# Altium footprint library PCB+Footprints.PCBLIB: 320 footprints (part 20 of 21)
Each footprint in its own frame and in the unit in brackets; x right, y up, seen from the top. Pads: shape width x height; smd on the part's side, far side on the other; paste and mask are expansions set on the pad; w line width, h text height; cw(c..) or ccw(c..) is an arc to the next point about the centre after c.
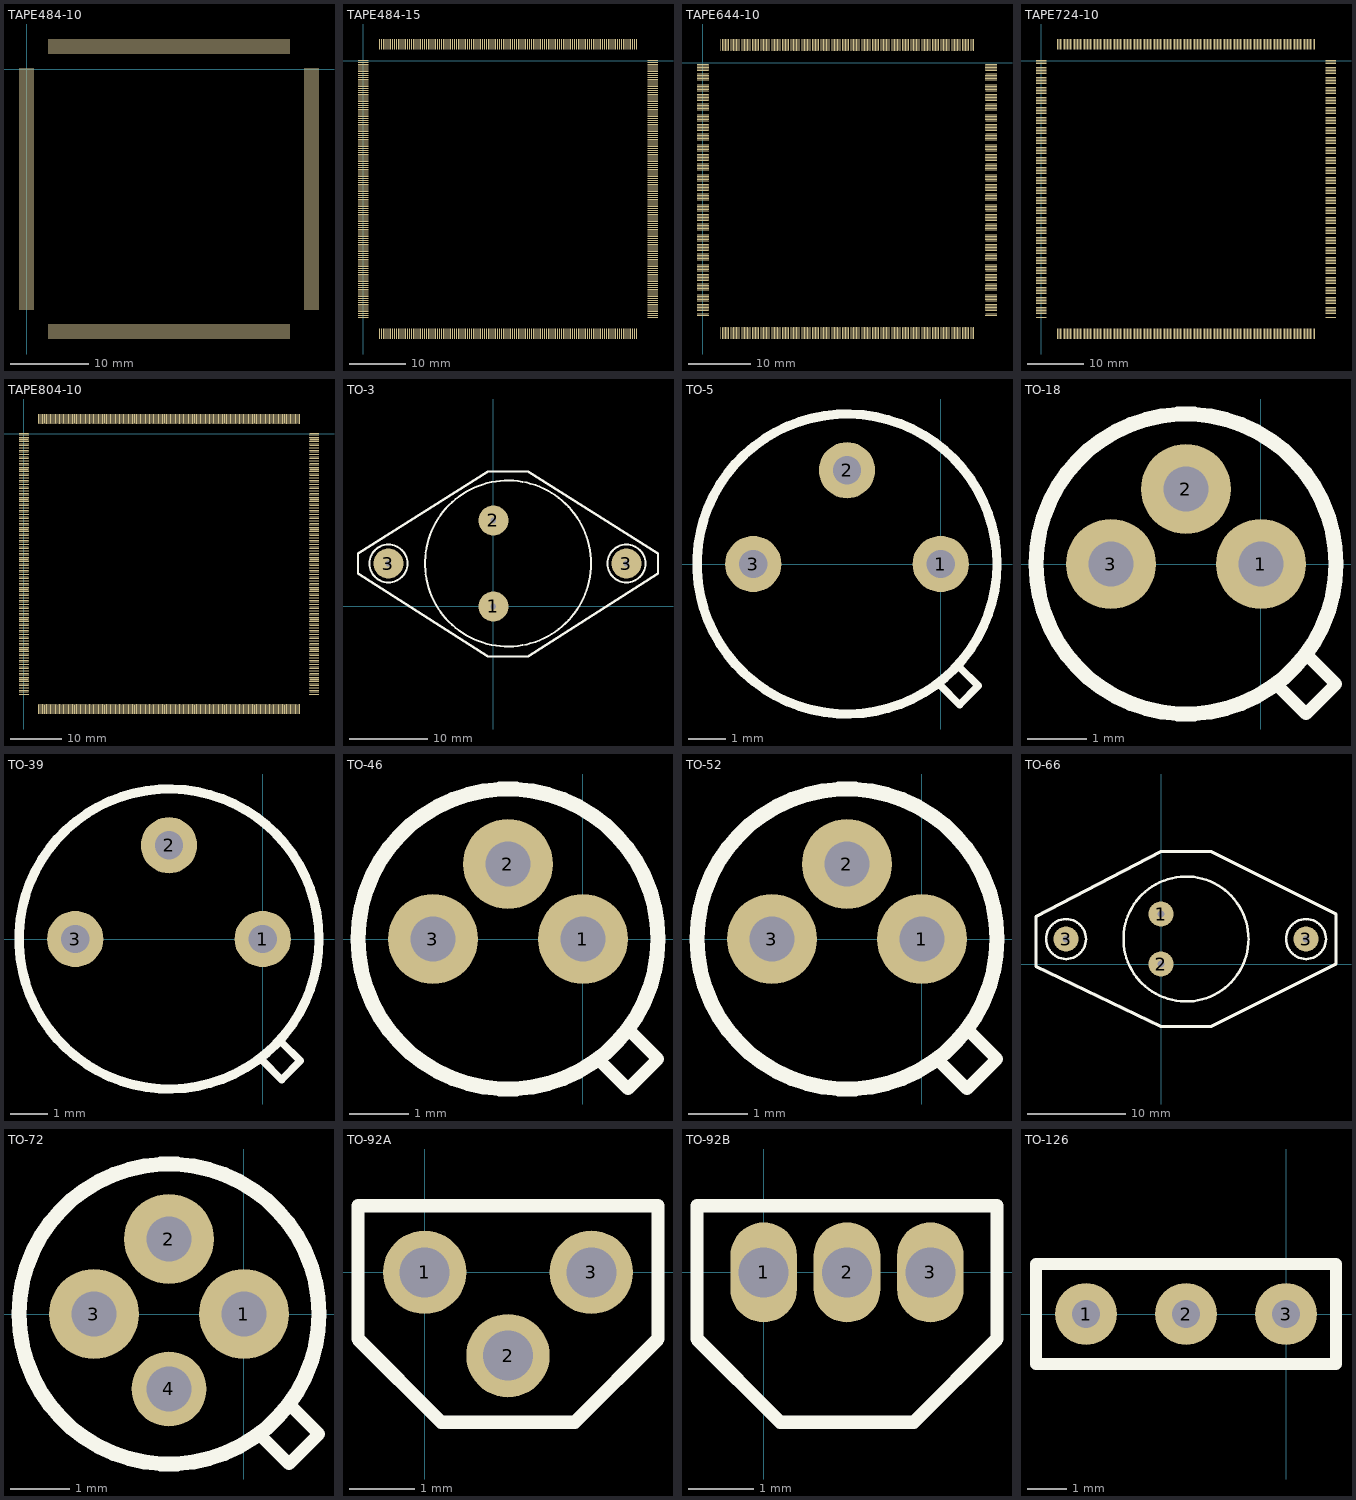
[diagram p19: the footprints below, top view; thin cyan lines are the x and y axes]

## TAPE484-10 [mil]
pads (484):
  oval 75x5 smd: 1(0,0) 2(0,-10) 3(0,-20) 4(0,-30) 5(0,-40) 6(0,-50) 7(0,-60) 8(0,-70) 9(0,-80) 10(0,-90) 11(0,-100) 12(0,-110) 13(0,-120) 14(0,-130) 15(0,-140) 16(0,-150) 17(0,-160) 18(0,-170) 19(0,-180) 20(0,-190) 21(0,-200) 22(0,-210) 23(0,-220) 24(0,-230) 25(0,-240) 26(0,-250) 27(0,-260) 28(0,-270) 29(0,-280) 30(0,-290) 31(0,-300) 32(0,-310) 33(0,-320) 34(0,-330) 35(0,-340) 36(0,-350) 37(0,-360) 38(0,-370) 39(0,-380) 40(0,-390) 41(0,-400) 42(0,-410) 43(0,-420) 44(0,-430) 45(0,-440) 46(0,-450) 47(0,-460) 48(0,-470) 49(0,-480) 50(0,-490) 51(0,-500) 52(0,-510) 53(0,-520) 54(0,-530) 55(0,-540) 56(0,-550) 57(0,-560) 58(0,-570) 59(0,-580) 60(0,-590) 61(0,-600) 62(0,-610) 63(0,-620) 64(0,-630) 65(0,-640) 66(0,-650) 67(0,-660) 68(0,-670) 69(0,-680) 70(0,-690) 71(0,-700) 72(0,-710) 73(0,-720) 74(0,-730) 75(0,-740) 76(0,-750) 77(0,-760) 78(0,-770) 79(0,-780) 80(0,-790) 81(0,-800) 82(0,-810) 83(0,-820) 84(0,-830) 85(0,-840) 86(0,-850) 87(0,-860) 88(0,-870) 89(0,-880) 90(0,-890) 91(0,-900) 92(0,-910) 93(0,-920) 94(0,-930) 95(0,-940) 96(0,-950) 97(0,-960) 98(0,-970) 99(0,-980) 100(0,-990) 101(0,-1000) 102(0,-1010) 103(0,-1020) 104(0,-1030) 105(0,-1040) 106(0,-1050) 107(0,-1060) 108(0,-1070) 109(0,-1080) 110(0,-1090) 111(0,-1100) 112(0,-1110) 113(0,-1120) 114(0,-1130) 115(0,-1140) 116(0,-1150) 117(0,-1160) 118(0,-1170) 119(0,-1180) 120(0,-1190) 121(0,-1200) 243(1425,-1200) 244(1425,-1190) 245(1425,-1180) 246(1425,-1170) 247(1425,-1160) 248(1425,-1150) 249(1425,-1140) 250(1425,-1130) 251(1425,-1120) 252(1425,-1110) 253(1425,-1100) 254(1425,-1090) 255(1425,-1080) 256(1425,-1070) 257(1425,-1060) 258(1425,-1050) 259(1425,-1040) 260(1425,-1030) 261(1425,-1020) 262(1425,-1010) 263(1425,-1000) 264(1425,-990) 265(1425,-980) 266(1425,-970) 267(1425,-960) 268(1425,-950) 269(1425,-940) 270(1425,-930) 271(1425,-920) 272(1425,-910) 273(1425,-900) 274(1425,-890) 275(1425,-880) 276(1425,-870) 277(1425,-860) 278(1425,-850) 279(1425,-840) 280(1425,-830) 281(1425,-820) 282(1425,-810) 283(1425,-800) 284(1425,-790) 285(1425,-780) 286(1425,-770) 287(1425,-760) 288(1425,-750) 289(1425,-740) 290(1425,-730) 291(1425,-720) 292(1425,-710) 293(1425,-700) 294(1425,-690) 295(1425,-680) 296(1425,-670) 297(1425,-660) 298(1425,-650) 299(1425,-640) 300(1425,-630) 301(1425,-620) 302(1425,-610) 303(1425,-600) 304(1425,-590) 305(1425,-580) 306(1425,-570) 307(1425,-560) 308(1425,-550) 309(1425,-540) 310(1425,-530) 311(1425,-520) 312(1425,-510) 313(1425,-500) 314(1425,-490) 315(1425,-480) 316(1425,-470) 317(1425,-460) 318(1425,-450) 319(1425,-440) 320(1425,-430) 321(1425,-420) 322(1425,-410) 323(1425,-400) 324(1425,-390) 325(1425,-380) 326(1425,-370) 327(1425,-360) 328(1425,-350) 329(1425,-340) 330(1425,-330) 331(1425,-320) 332(1425,-310) 333(1425,-300) 334(1425,-290) 335(1425,-280) 336(1425,-270) 337(1425,-260) 338(1425,-250) 339(1425,-240) 340(1425,-230) 341(1425,-220) 342(1425,-210) 343(1425,-200) 344(1425,-190) 345(1425,-180) 346(1425,-170) 347(1425,-160) 348(1425,-150) 349(1425,-140) 350(1425,-130) 351(1425,-120) 352(1425,-110) 353(1425,-100) 354(1425,-90) 355(1425,-80) 356(1425,-70) 357(1425,-60) 358(1425,-50) 359(1425,-40) 360(1425,-30) 361(1425,-20) 362(1425,-10) 363(1425,0)
  oval 5x75 smd: 122(113,-1312) 123(123,-1312) 124(133,-1312) 125(143,-1312) 126(153,-1312) 127(163,-1312) 128(173,-1312) 129(183,-1312) 130(193,-1312) 131(203,-1312) 132(213,-1312) 133(223,-1312) 134(233,-1312) 135(243,-1312) 136(253,-1312) 137(263,-1312) 138(273,-1312) 139(283,-1312) 140(293,-1312) 141(303,-1312) 142(313,-1312) 143(323,-1312) 144(333,-1312) 145(343,-1312) 146(353,-1312) 147(363,-1312) 148(373,-1312) 149(383,-1312) 150(393,-1312) 151(403,-1312) 152(413,-1312) 153(423,-1312) 154(433,-1312) 155(443,-1312) 156(453,-1312) 157(463,-1312) 158(473,-1312) 159(483,-1312) 160(493,-1312) 161(503,-1312) 162(513,-1312) 163(523,-1312) 164(533,-1312) 165(543,-1312) 166(553,-1312) 167(563,-1312) 168(573,-1312) 169(583,-1312) 170(593,-1312) 171(603,-1312) 172(613,-1312) 173(623,-1312) 174(633,-1312) 175(643,-1312) 176(653,-1312) 177(663,-1312) 178(673,-1312) 179(683,-1312) 180(693,-1312) 181(703,-1312) 182(713,-1312) 183(723,-1312) 184(733,-1312) 185(743,-1312) 186(753,-1312) 187(763,-1312) 188(773,-1312) 189(783,-1312) 190(793,-1312) 191(803,-1312) 192(813,-1312) 193(823,-1312) 194(833,-1312) 195(843,-1312) 196(853,-1312) 197(863,-1312) 198(873,-1312) 199(883,-1312) 200(893,-1312) 201(903,-1312) 202(913,-1312) 203(923,-1312) 204(933,-1312) 205(943,-1312) 206(953,-1312) 207(963,-1312) 208(973,-1312) 209(983,-1312) 210(993,-1312) 211(1003,-1312) 212(1013,-1312) 213(1023,-1312) 214(1033,-1312) 215(1043,-1312) 216(1053,-1312) 217(1063,-1312) 218(1073,-1312) 219(1083,-1312) 220(1093,-1312) 221(1103,-1312) 222(1113,-1312) 223(1123,-1312) 224(1133,-1312) 225(1143,-1312) 226(1153,-1312) 227(1163,-1312) 228(1173,-1312) 229(1183,-1312) 230(1193,-1312) 231(1203,-1312) 232(1213,-1312) 233(1223,-1312) 234(1233,-1312) 235(1243,-1312) 236(1253,-1312) 237(1263,-1312) 238(1273,-1312) 239(1283,-1312) 240(1293,-1312) 241(1303,-1312) 242(1313,-1312) 364(1313,113) 365(1303,113) 366(1293,113) 367(1283,113) 368(1273,113) 369(1263,113) 370(1253,113) 371(1243,113) 372(1233,113) 373(1223,113) 374(1213,113) 375(1203,113) 376(1193,113) 377(1183,113) 378(1173,113) 379(1163,113) 380(1153,113) 381(1143,113) 382(1133,113) 383(1123,113) 384(1113,113) 385(1103,113) 386(1093,113) 387(1083,113) 388(1073,113) 389(1063,113) 390(1053,113) 391(1043,113) 392(1033,113) 393(1023,113) 394(1013,113) 395(1003,113) 396(993,113) 397(983,113) 398(973,113) 399(963,113) 400(953,113) 401(943,113) 402(933,113) 403(923,113) 404(913,113) 405(903,113) 406(893,113) 407(883,113) 408(873,113) 409(863,113) 410(853,113) 411(843,113) 412(833,113) 413(823,113) 414(813,113) 415(803,113) 416(793,113) 417(783,113) 418(773,113) 419(763,113) 420(753,113) 421(743,113) 422(733,113) 423(723,113) 424(713,113) 425(703,113) 426(693,113) 427(683,113) 428(673,113) 429(663,113) 430(653,113) 431(643,113) 432(633,113) 433(623,113) 434(613,113) 435(603,113) 436(593,113) 437(583,113) 438(573,113) 439(563,113) 440(553,113) 441(543,113) 442(533,113) 443(523,113) 444(513,113) 445(503,113) 446(493,113) 447(483,113) 448(473,113) 449(463,113) 450(453,113) 451(443,113) 452(433,113) 453(423,113) 454(413,113) 455(403,113) 456(393,113) 457(383,113) 458(373,113) 459(363,113) 460(353,113) 461(343,113) 462(333,113) 463(323,113) 464(313,113) 465(303,113) 466(293,113) 467(283,113) 468(273,113) 469(263,113) 470(253,113) 471(243,113) 472(233,113) 473(223,113) 474(213,113) 475(203,113) 476(193,113) 477(183,113) 478(173,113) 479(163,113) 480(153,113) 481(143,113) 482(133,113) 483(123,113) 484(113,113)

## TAPE484-15 [mil]
pads (484):
  oval 75x8 smd: 1(0,0) 2(0,-15) 3(0,-30) 4(0,-45) 5(0,-60) 6(0,-75) 7(0,-90) 8(0,-105) 9(0,-120) 10(0,-135) 11(0,-150) 12(0,-165) 13(0,-180) 14(0,-195) 15(0,-210) 16(0,-225) 17(0,-240) 18(0,-255) 19(0,-270) 20(0,-285) 21(0,-300) 22(0,-315) 23(0,-330) 24(0,-345) 25(0,-360) 26(0,-375) 27(0,-390) 28(0,-405) 29(0,-420) 30(0,-435) 31(0,-450) 32(0,-465) 33(0,-480) 34(0,-495) 35(0,-510) 36(0,-525) 37(0,-540) 38(0,-555) 39(0,-570) 40(0,-585) 41(0,-600) 42(0,-615) 43(0,-630) 44(0,-645) 45(0,-660) 46(0,-675) 47(0,-690) 48(0,-705) 49(0,-720) 50(0,-735) 51(0,-750) 52(0,-765) 53(0,-780) 54(0,-795) 55(0,-810) 56(0,-825) 57(0,-840) 58(0,-855) 59(0,-870) 60(0,-885) 61(0,-900) 62(0,-915) 63(0,-930) 64(0,-945) 65(0,-960) 66(0,-975) 67(0,-990) 68(0,-1005) 69(0,-1020) 70(0,-1035) 71(0,-1050) 72(0,-1065) 73(0,-1080) 74(0,-1095) 75(0,-1110) 76(0,-1125) 77(0,-1140) 78(0,-1155) 79(0,-1170) 80(0,-1185) 81(0,-1200) 82(0,-1215) 83(0,-1230) 84(0,-1245) 85(0,-1260) 86(0,-1275) 87(0,-1290) 88(0,-1305) 89(0,-1320) 90(0,-1335) 91(0,-1350) 92(0,-1365) 93(0,-1380) 94(0,-1395) 95(0,-1410) 96(0,-1425) 97(0,-1440) 98(0,-1455) 99(0,-1470) 100(0,-1485) 101(0,-1500) 102(0,-1515) 103(0,-1530) 104(0,-1545) 105(0,-1560) 106(0,-1575) 107(0,-1590) 108(0,-1605) 109(0,-1620) 110(0,-1635) 111(0,-1650) 112(0,-1665) 113(0,-1680) 114(0,-1695) 115(0,-1710) 116(0,-1725) 117(0,-1740) 118(0,-1755) 119(0,-1770) 120(0,-1785) 121(0,-1800) 243(2025,-1800) 244(2025,-1785) 245(2025,-1770) 246(2025,-1755) 247(2025,-1740) 248(2025,-1725) 249(2025,-1710) 250(2025,-1695) 251(2025,-1680) 252(2025,-1665) 253(2025,-1650) 254(2025,-1635) 255(2025,-1620) 256(2025,-1605) 257(2025,-1590) 258(2025,-1575) 259(2025,-1560) 260(2025,-1545) 261(2025,-1530) 262(2025,-1515) 263(2025,-1500) 264(2025,-1485) 265(2025,-1470) 266(2025,-1455) 267(2025,-1440) 268(2025,-1425) 269(2025,-1410) 270(2025,-1395) 271(2025,-1380) 272(2025,-1365) 273(2025,-1350) 274(2025,-1335) 275(2025,-1320) 276(2025,-1305) 277(2025,-1290) 278(2025,-1275) 279(2025,-1260) 280(2025,-1245) 281(2025,-1230) 282(2025,-1215) 283(2025,-1200) 284(2025,-1185) 285(2025,-1170) 286(2025,-1155) 287(2025,-1140) 288(2025,-1125) 289(2025,-1110) 290(2025,-1095) 291(2025,-1080) 292(2025,-1065) 293(2025,-1050) 294(2025,-1035) 295(2025,-1020) 296(2025,-1005) 297(2025,-990) 298(2025,-975) 299(2025,-960) 300(2025,-945) 301(2025,-930) 302(2025,-915) 303(2025,-900) 304(2025,-885) 305(2025,-870) 306(2025,-855) 307(2025,-840) 308(2025,-825) 309(2025,-810) 310(2025,-795) 311(2025,-780) 312(2025,-765) 313(2025,-750) 314(2025,-735) 315(2025,-720) 316(2025,-705) 317(2025,-690) 318(2025,-675) 319(2025,-660) 320(2025,-645) 321(2025,-630) 322(2025,-615) 323(2025,-600) 324(2025,-585) 325(2025,-570) 326(2025,-555) 327(2025,-540) 328(2025,-525) 329(2025,-510) 330(2025,-495) 331(2025,-480) 332(2025,-465) 333(2025,-450) 334(2025,-435) 335(2025,-420) 336(2025,-405) 337(2025,-390) 338(2025,-375) 339(2025,-360) 340(2025,-345) 341(2025,-330) 342(2025,-315) 343(2025,-300) 344(2025,-285) 345(2025,-270) 346(2025,-255) 347(2025,-240) 348(2025,-225) 349(2025,-210) 350(2025,-195) 351(2025,-180) 352(2025,-165) 353(2025,-150) 354(2025,-135) 355(2025,-120) 356(2025,-105) 357(2025,-90) 358(2025,-75) 359(2025,-60) 360(2025,-45) 361(2025,-30) 362(2025,-15) 363(2025,0)
  oval 8x75 smd: 122(113,-1912) 123(128,-1912) 124(143,-1912) 125(158,-1912) 126(173,-1912) 127(188,-1912) 128(203,-1912) 129(218,-1912) 130(233,-1912) 131(248,-1912) 132(263,-1912) 133(278,-1912) 134(293,-1912) 135(308,-1912) 136(323,-1912) 137(338,-1912) 138(353,-1912) 139(368,-1912) 140(383,-1912) 141(398,-1912) 142(413,-1912) 143(428,-1912) 144(443,-1912) 145(458,-1912) 146(473,-1912) 147(488,-1912) 148(503,-1912) 149(518,-1912) 150(533,-1912) 151(548,-1912) 152(563,-1912) 153(578,-1912) 154(593,-1912) 155(608,-1912) 156(623,-1912) 157(638,-1912) 158(653,-1912) 159(668,-1912) 160(683,-1912) 161(698,-1912) 162(713,-1912) 163(728,-1912) 164(743,-1912) 165(758,-1912) 166(773,-1912) 167(788,-1912) 168(803,-1912) 169(818,-1912) 170(833,-1912) 171(848,-1912) 172(863,-1912) 173(878,-1912) 174(893,-1912) 175(908,-1912) 176(923,-1912) 177(938,-1912) 178(953,-1912) 179(968,-1912) 180(983,-1912) 181(998,-1912) 182(1013,-1912) 183(1028,-1912) 184(1043,-1912) 185(1058,-1912) 186(1073,-1912) 187(1088,-1912) 188(1103,-1912) 189(1118,-1912) 190(1133,-1912) 191(1148,-1912) 192(1163,-1912) 193(1178,-1912) 194(1193,-1912) 195(1208,-1912) 196(1223,-1912) 197(1238,-1912) 198(1253,-1912) 199(1268,-1912) 200(1283,-1912) 201(1298,-1912) 202(1313,-1912) 203(1328,-1912) 204(1343,-1912) 205(1358,-1912) 206(1373,-1912) 207(1388,-1912) 208(1403,-1912) 209(1418,-1912) 210(1433,-1912) 211(1448,-1912) 212(1463,-1912) 213(1478,-1912) 214(1493,-1912) 215(1508,-1912) 216(1523,-1912) 217(1538,-1912) 218(1553,-1912) 219(1568,-1912) 220(1583,-1912) 221(1598,-1912) 222(1613,-1912) 223(1628,-1912) 224(1643,-1912) 225(1658,-1912) 226(1673,-1912) 227(1688,-1912) 228(1703,-1912) 229(1718,-1912) 230(1733,-1912) 231(1748,-1912) 232(1763,-1912) 233(1778,-1912) 234(1793,-1912) 235(1808,-1912) 236(1823,-1912) 237(1838,-1912) 238(1853,-1912) 239(1868,-1912) 240(1883,-1912) 241(1898,-1912) 242(1913,-1912) 364(1913,113) 365(1898,113) 366(1883,113) 367(1868,113) 368(1853,113) 369(1838,113) 370(1823,113) 371(1808,113) 372(1793,113) 373(1778,113) 374(1763,113) 375(1748,113) 376(1733,113) 377(1718,113) 378(1703,113) 379(1688,113) 380(1673,113) 381(1658,113) 382(1643,113) 383(1628,113) 384(1613,113) 385(1598,113) 386(1583,113) 387(1568,113) 388(1553,113) 389(1538,113) 390(1523,113) 391(1508,113) 392(1493,113) 393(1478,113) 394(1463,113) 395(1448,113) 396(1433,113) 397(1418,113) 398(1403,113) 399(1388,113) 400(1373,113) 401(1358,113) 402(1343,113) 403(1328,113) 404(1313,113) 405(1298,113) 406(1283,113) 407(1268,113) 408(1253,113) 409(1238,113) 410(1223,113) 411(1208,113) 412(1193,113) 413(1178,113) 414(1163,113) 415(1148,113) 416(1133,113) 417(1118,113) 418(1103,113) 419(1088,113) 420(1073,113) 421(1058,113) 422(1043,113) 423(1028,113) 424(1013,113) 425(998,113) 426(983,113) 427(968,113) 428(953,113) 429(938,113) 430(923,113) 431(908,113) 432(893,113) 433(878,113) 434(863,113) 435(848,113) 436(833,113) 437(818,113) 438(803,113) 439(788,113) 440(773,113) 441(758,113) 442(743,113) 443(728,113) 444(713,113) 445(698,113) 446(683,113) 447(668,113) 448(653,113) 449(638,113) 450(623,113) 451(608,113) 452(593,113) 453(578,113) 454(563,113) 455(548,113) 456(533,113) 457(518,113) 458(503,113) 459(488,113) 460(473,113) 461(458,113) 462(443,113) 463(428,113) 464(413,113) 465(398,113) 466(383,113) 467(368,113) 468(353,113) 469(338,113) 470(323,113) 471(308,113) 472(293,113) 473(278,113) 474(263,113) 475(248,113) 476(233,113) 477(218,113) 478(203,113) 479(188,113) 480(173,113) 481(158,113) 482(143,113) 483(128,113) 484(113,113)

## TAPE644-10 [mil]
pads (644):
  oval 75x5 smd: 1(0,0) 2(0,-10) 3(0,-20) 4(0,-30) 5(0,-40) 6(0,-50) 7(0,-60) 8(0,-70) 9(0,-80) 10(0,-90) 11(0,-100) 12(0,-110) 13(0,-120) 14(0,-130) 15(0,-140) 16(0,-150) 17(0,-160) 18(0,-170) 19(0,-180) 20(0,-190) 21(0,-200) 22(0,-210) 23(0,-220) 24(0,-230) 25(0,-240) 26(0,-250) 27(0,-260) 28(0,-270) 29(0,-280) 30(0,-290) 31(0,-300) 32(0,-310) 33(0,-320) 34(0,-330) 35(0,-340) 36(0,-350) 37(0,-360) 38(0,-370) 39(0,-380) 40(0,-390) 41(0,-400) 42(0,-410) 43(0,-420) 44(0,-430) 45(0,-440) 46(0,-450) 47(0,-460) 48(0,-470) 49(0,-480) 50(0,-490) 51(0,-500) 52(0,-510) 53(0,-520) 54(0,-530) 55(0,-540) 56(0,-550) 57(0,-560) 58(0,-570) 59(0,-580) 60(0,-590) 61(0,-600) 62(0,-610) 63(0,-620) 64(0,-630) 65(0,-640) 66(0,-650) 67(0,-660) 68(0,-670) 69(0,-680) 70(0,-690) 71(0,-700) 72(0,-710) 73(0,-720) 74(0,-730) 75(0,-740) 76(0,-750) 77(0,-760) 78(0,-770) 79(0,-780) 80(0,-790) 81(0,-800) 82(0,-810) 83(0,-820) 84(0,-830) 85(0,-840) 86(0,-850) 87(0,-860) 88(0,-870) 89(0,-880) 90(0,-890) 91(0,-900) 92(0,-910) 93(0,-920) 94(0,-930) 95(0,-940) 96(0,-950) 97(0,-960) 98(0,-970) 99(0,-980) 100(0,-990) 101(0,-1000) 102(0,-1010) 103(0,-1020) 104(0,-1030) 105(0,-1040) 106(0,-1050) 107(0,-1060) 108(0,-1070) 109(0,-1080) 110(0,-1090) 111(0,-1100) 112(0,-1110) 113(0,-1120) 114(0,-1130) 115(0,-1140) 116(0,-1150) 117(0,-1160) 118(0,-1170) 119(0,-1180) 120(0,-1190) 121(0,-1200) 122(0,-1210) 123(0,-1220) 124(0,-1230) 125(0,-1240) 126(0,-1250) 127(0,-1260) 128(0,-1270) 129(0,-1280) 130(0,-1290) 131(0,-1300) 132(0,-1310) 133(0,-1320) 134(0,-1330) 135(0,-1340) 136(0,-1350) 137(0,-1360) 138(0,-1370) 139(0,-1380) 140(0,-1390) 141(0,-1400) 142(0,-1410) 143(0,-1420) 144(0,-1430) 145(0,-1440) 146(0,-1450) 147(0,-1460) 148(0,-1470) 149(0,-1480) 150(0,-1490) 151(0,-1500) 152(0,-1510) 153(0,-1520) 154(0,-1530) 155(0,-1540) 156(0,-1550) 157(0,-1560) 158(0,-1570) 159(0,-1580) 160(0,-1590) 161(0,-1600) 323(1825,-1600) 324(1825,-1590) 325(1825,-1580) 326(1825,-1570) 327(1825,-1560) 328(1825,-1550) 329(1825,-1540) 330(1825,-1530) 331(1825,-1520) 332(1825,-1510) 333(1825,-1500) 334(1825,-1490) 335(1825,-1480) 336(1825,-1470) 337(1825,-1460) 338(1825,-1450) 339(1825,-1440) 340(1825,-1430) 341(1825,-1420) 342(1825,-1410) 343(1825,-1400) 344(1825,-1390) 345(1825,-1380) 346(1825,-1370) 347(1825,-1360) 348(1825,-1350) 349(1825,-1340) 350(1825,-1330) 351(1825,-1320) 352(1825,-1310) 353(1825,-1300) 354(1825,-1290) 355(1825,-1280) 356(1825,-1270) 357(1825,-1260) 358(1825,-1250) 359(1825,-1240) 360(1825,-1230) 361(1825,-1220) 362(1825,-1210) 363(1825,-1200) 364(1825,-1190) 365(1825,-1180) 366(1825,-1170) 367(1825,-1160) 368(1825,-1150) 369(1825,-1140) 370(1825,-1130) 371(1825,-1120) 372(1825,-1110) 373(1825,-1100) 374(1825,-1090) 375(1825,-1080) 376(1825,-1070) 377(1825,-1060) 378(1825,-1050) 379(1825,-1040) 380(1825,-1030) 381(1825,-1020) 382(1825,-1010) 383(1825,-1000) 384(1825,-990) 385(1825,-980) 386(1825,-970) 387(1825,-960) 388(1825,-950) 389(1825,-940) 390(1825,-930) 391(1825,-920) 392(1825,-910) 393(1825,-900) 394(1825,-890) 395(1825,-880) 396(1825,-870) 397(1825,-860) 398(1825,-850) 399(1825,-840) 400(1825,-830) 401(1825,-820) 402(1825,-810) 403(1825,-800) 404(1825,-790) 405(1825,-780) 406(1825,-770) 407(1825,-760) 408(1825,-750) 409(1825,-740) 410(1825,-730) 411(1825,-720) 412(1825,-710) 413(1825,-700) 414(1825,-690) 415(1825,-680) 416(1825,-670) 417(1825,-660) 418(1825,-650) 419(1825,-640) 420(1825,-630) 421(1825,-620) 422(1825,-610) 423(1825,-600) 424(1825,-590) 425(1825,-580) 426(1825,-570) 427(1825,-560) 428(1825,-550) 429(1825,-540) 430(1825,-530) 431(1825,-520) 432(1825,-510) 433(1825,-500) 434(1825,-490) 435(1825,-480) 436(1825,-470) 437(1825,-460) 438(1825,-450) 439(1825,-440) 440(1825,-430) 441(1825,-420) 442(1825,-410) 443(1825,-400) 444(1825,-390) 445(1825,-380) 446(1825,-370) 447(1825,-360) 448(1825,-350) 449(1825,-340) 450(1825,-330) 451(1825,-320) 452(1825,-310) 453(1825,-300) 454(1825,-290) 455(1825,-280) 456(1825,-270) 457(1825,-260) 458(1825,-250) 459(1825,-240) 460(1825,-230) 461(1825,-220) 462(1825,-210) 463(1825,-200) 464(1825,-190) 465(1825,-180) 466(1825,-170) 467(1825,-160) 468(1825,-150) 469(1825,-140) 470(1825,-130) 471(1825,-120) 472(1825,-110) 473(1825,-100) 474(1825,-90) 475(1825,-80) 476(1825,-70) 477(1825,-60) 478(1825,-50) 479(1825,-40) 480(1825,-30) 481(1825,-20) 482(1825,-10) 483(1825,0)
  oval 5x75 smd: 162(113,-1712) 163(123,-1712) 164(133,-1712) 165(143,-1712) 166(153,-1712) 167(163,-1712) 168(173,-1712) 169(183,-1712) 170(193,-1712) 171(203,-1712) 172(213,-1712) 173(223,-1712) 174(233,-1712) 175(243,-1712) 176(253,-1712) 177(263,-1712) 178(273,-1712) 179(283,-1712) 180(293,-1712) 181(303,-1712) 182(313,-1712) 183(323,-1712) 184(333,-1712) 185(343,-1712) 186(353,-1712) 187(363,-1712) 188(373,-1712) 189(383,-1712) 190(393,-1712) 191(403,-1712) 192(413,-1712) 193(423,-1712) 194(433,-1712) 195(443,-1712) 196(453,-1712) 197(463,-1712) 198(473,-1712) 199(483,-1712) 200(493,-1712) 201(503,-1712) 202(513,-1712) 203(523,-1712) 204(533,-1712) 205(543,-1712) 206(553,-1712) 207(563,-1712) 208(573,-1712) 209(583,-1712) 210(593,-1712) 211(603,-1712) 212(613,-1712) 213(623,-1712) 214(633,-1712) 215(643,-1712) 216(653,-1712) 217(663,-1712) 218(673,-1712) 219(683,-1712) 220(693,-1712) 221(703,-1712) 222(713,-1712) 223(723,-1712) 224(733,-1712) 225(743,-1712) 226(753,-1712) 227(763,-1712) 228(773,-1712) 229(783,-1712) 230(793,-1712) 231(803,-1712) 232(813,-1712) 233(823,-1712) 234(833,-1712) 235(843,-1712) 236(853,-1712) 237(863,-1712) 238(873,-1712) 239(883,-1712) 240(893,-1712) 241(903,-1712) 242(913,-1712) 243(923,-1712) 244(933,-1712) 245(943,-1712) 246(953,-1712) 247(963,-1712) 248(973,-1712) 249(983,-1712) 250(993,-1712) 251(1003,-1712) 252(1013,-1712) 253(1023,-1712) 254(1033,-1712) 255(1043,-1712) 256(1053,-1712) 257(1063,-1712) 258(1073,-1712) 259(1083,-1712) 260(1093,-1712) 261(1103,-1712) 262(1113,-1712) 263(1123,-1712) 264(1133,-1712) 265(1143,-1712) 266(1153,-1712) 267(1163,-1712) 268(1173,-1712) 269(1183,-1712) 270(1193,-1712) 271(1203,-1712) 272(1213,-1712) 273(1223,-1712) 274(1233,-1712) 275(1243,-1712) 276(1253,-1712) 277(1263,-1712) 278(1273,-1712) 279(1283,-1712) 280(1293,-1712) 281(1303,-1712) 282(1313,-1712) 283(1323,-1712) 284(1333,-1712) 285(1343,-1712) 286(1353,-1712) 287(1363,-1712) 288(1373,-1712) 289(1383,-1712) 290(1393,-1712) 291(1403,-1712) 292(1413,-1712) 293(1423,-1712) 294(1433,-1712) 295(1443,-1712) 296(1453,-1712) 297(1463,-1712) 298(1473,-1712) 299(1483,-1712) 300(1493,-1712) 301(1503,-1712) 302(1513,-1712) 303(1523,-1712) 304(1533,-1712) 305(1543,-1712) 306(1553,-1712) 307(1563,-1712) 308(1573,-1712) 309(1583,-1712) 310(1593,-1712) 311(1603,-1712) 312(1613,-1712) 313(1623,-1712) 314(1633,-1712) 315(1643,-1712) 316(1653,-1712) 317(1663,-1712) 318(1673,-1712) 319(1683,-1712) 320(1693,-1712) 321(1703,-1712) 322(1713,-1712) 484(1713,113) 485(1703,113) 486(1693,113) 487(1683,113) 488(1673,113) 489(1663,113) 490(1653,113) 491(1643,113) 492(1633,113) 493(1623,113) 494(1613,113) 495(1603,113) 496(1593,113) 497(1583,113) 498(1573,113) 499(1563,113) 500(1553,113) 501(1543,113) 502(1533,113) 503(1523,113) 504(1513,113) 505(1503,113) 506(1493,113) 507(1483,113) 508(1473,113) 509(1463,113) 510(1453,113) 511(1443,113) 512(1433,113) 513(1423,113) 514(1413,113) 515(1403,113) 516(1393,113) 517(1383,113) 518(1373,113) 519(1363,113) 520(1353,113) 521(1343,113) 522(1333,113) 523(1323,113) 524(1313,113) 525(1303,113) 526(1293,113) 527(1283,113) 528(1273,113) 529(1263,113) 530(1253,113) 531(1243,113) 532(1233,113) 533(1223,113) 534(1213,113) 535(1203,113) 536(1193,113) 537(1183,113) 538(1173,113) 539(1163,113) 540(1153,113) 541(1143,113) 542(1133,113) 543(1123,113) 544(1113,113) 545(1103,113) 546(1093,113) 547(1083,113) 548(1073,113) 549(1063,113) 550(1053,113) 551(1043,113) 552(1033,113) 553(1023,113) 554(1013,113) 555(1003,113) 556(993,113) 557(983,113) 558(973,113) 559(963,113) 560(953,113) 561(943,113) 562(933,113) 563(923,113) 564(913,113) 565(903,113) 566(893,113) 567(883,113) 568(873,113) 569(863,113) 570(853,113) 571(843,113) 572(833,113) 573(823,113) 574(813,113) 575(803,113) 576(793,113) 577(783,113) 578(773,113) 579(763,113) 580(753,113) 581(743,113) 582(733,113) 583(723,113) 584(713,113) 585(703,113) 586(693,113) 587(683,113) 588(673,113) 589(663,113) 590(653,113) 591(643,113) 592(633,113) 593(623,113) 594(613,113) 595(603,113) 596(593,113) 597(583,113) 598(573,113) 599(563,113) 600(553,113) 601(543,113) 602(533,113) 603(523,113) 604(513,113) 605(503,113) 606(493,113) 607(483,113) 608(473,113) 609(463,113) 610(453,113) 611(443,113) 612(433,113) 613(423,113) 614(413,113) 615(403,113) 616(393,113) 617(383,113) 618(373,113) 619(363,113) 620(353,113) 621(343,113) 622(333,113) 623(323,113) 624(313,113) 625(303,113) 626(293,113) 627(283,113) 628(273,113) 629(263,113) 630(253,113) 631(243,113) 632(233,113) 633(223,113) 634(213,113) 635(203,113) 636(193,113) 637(183,113) 638(173,113) 639(163,113) 640(153,113) 641(143,113) 642(133,113) 643(123,113) 644(113,113)

## TAPE724-10 [mil]
pads (724):
  oval 75x5 smd: 1(0,0) 2(0,-10) 3(0,-20) 4(0,-30) 5(0,-40) 6(0,-50) 7(0,-60) 8(0,-70) 9(0,-80) 10(0,-90) 11(0,-100) 12(0,-110) 13(0,-120) 14(0,-130) 15(0,-140) 16(0,-150) 17(0,-160) 18(0,-170) 19(0,-180) 20(0,-190) 21(0,-200) 22(0,-210) 23(0,-220) 24(0,-230) 25(0,-240) 26(0,-250) 27(0,-260) 28(0,-270) 29(0,-280) 30(0,-290) 31(0,-300) 32(0,-310) 33(0,-320) 34(0,-330) 35(0,-340) 36(0,-350) 37(0,-360) 38(0,-370) 39(0,-380) 40(0,-390) 41(0,-400) 42(0,-410) 43(0,-420) 44(0,-430) 45(0,-440) 46(0,-450) 47(0,-460) 48(0,-470) 49(0,-480) 50(0,-490) 51(0,-500) 52(0,-510) 53(0,-520) 54(0,-530) 55(0,-540) 56(0,-550) 57(0,-560) 58(0,-570) 59(0,-580) 60(0,-590) 61(0,-600) 62(0,-610) 63(0,-620) 64(0,-630) 65(0,-640) 66(0,-650) 67(0,-660) 68(0,-670) 69(0,-680) 70(0,-690) 71(0,-700) 72(0,-710) 73(0,-720) 74(0,-730) 75(0,-740) 76(0,-750) 77(0,-760) 78(0,-770) 79(0,-780) 80(0,-790) 81(0,-800) 82(0,-810) 83(0,-820) 84(0,-830) 85(0,-840) 86(0,-850) 87(0,-860) 88(0,-870) 89(0,-880) 90(0,-890) 91(0,-900) 92(0,-910) 93(0,-920) 94(0,-930) 95(0,-940) 96(0,-950) 97(0,-960) 98(0,-970) 99(0,-980) 100(0,-990) 101(0,-1000) 102(0,-1010) 103(0,-1020) 104(0,-1030) 105(0,-1040) 106(0,-1050) 107(0,-1060) 108(0,-1070) 109(0,-1080) 110(0,-1090) 111(0,-1100) 112(0,-1110) 113(0,-1120) 114(0,-1130) 115(0,-1140) 116(0,-1150) 117(0,-1160) 118(0,-1170) 119(0,-1180) 120(0,-1190) 121(0,-1200) 122(0,-1210) 123(0,-1220) 124(0,-1230) 125(0,-1240) 126(0,-1250) 127(0,-1260) 128(0,-1270) 129(0,-1280) 130(0,-1290) 131(0,-1300) 132(0,-1310) 133(0,-1320) 134(0,-1330) 135(0,-1340) 136(0,-1350) 137(0,-1360) 138(0,-1370) 139(0,-1380) 140(0,-1390) 141(0,-1400) 142(0,-1410) 143(0,-1420) 144(0,-1430) 145(0,-1440) 146(0,-1450) 147(0,-1460) 148(0,-1470) 149(0,-1480) 150(0,-1490) 151(0,-1500) 152(0,-1510) 153(0,-1520) 154(0,-1530) 155(0,-1540) 156(0,-1550) 157(0,-1560) 158(0,-1570) 159(0,-1580) 160(0,-1590) 161(0,-1600) 162(0,-1610) 163(0,-1620) 164(0,-1630) 165(0,-1640) 166(0,-1650) 167(0,-1660) 168(0,-1670) 169(0,-1680) 170(0,-1690) 171(0,-1700) 172(0,-1710) 173(0,-1720) 174(0,-1730) 175(0,-1740) 176(0,-1750) 177(0,-1760) 178(0,-1770) 179(0,-1780) 180(0,-1790) 181(0,-1800) 363(2025,-1800) 364(2025,-1790) 365(2025,-1780) 366(2025,-1770) 367(2025,-1760) 368(2025,-1750) 369(2025,-1740) 370(2025,-1730) 371(2025,-1720) 372(2025,-1710) 373(2025,-1700) 374(2025,-1690) 375(2025,-1680) 376(2025,-1670) 377(2025,-1660) 378(2025,-1650) 379(2025,-1640) 380(2025,-1630) 381(2025,-1620) 382(2025,-1610) 383(2025,-1600) 384(2025,-1590) 385(2025,-1580) 386(2025,-1570) 387(2025,-1560) 388(2025,-1550) 389(2025,-1540) 390(2025,-1530) 391(2025,-1520) 392(2025,-1510) 393(2025,-1500) 394(2025,-1490) 395(2025,-1480) 396(2025,-1470) 397(2025,-1460) 398(2025,-1450) 399(2025,-1440) 400(2025,-1430) 401(2025,-1420) 402(2025,-1410) 403(2025,-1400) 404(2025,-1390) 405(2025,-1380) 406(2025,-1370) 407(2025,-1360) 408(2025,-1350) 409(2025,-1340) 410(2025,-1330) 411(2025,-1320) 412(2025,-1310) 413(2025,-1300) 414(2025,-1290) 415(2025,-1280) 416(2025,-1270) 417(2025,-1260) 418(2025,-1250) 419(2025,-1240) 420(2025,-1230) 421(2025,-1220) 422(2025,-1210) 423(2025,-1200) 424(2025,-1190) 425(2025,-1180) 426(2025,-1170) 427(2025,-1160) 428(2025,-1150) 429(2025,-1140) 430(2025,-1130) 431(2025,-1120) 432(2025,-1110) 433(2025,-1100) 434(2025,-1090) 435(2025,-1080) 436(2025,-1070) 437(2025,-1060) 438(2025,-1050) 439(2025,-1040) 440(2025,-1030) 441(2025,-1020) 442(2025,-1010) 443(2025,-1000) 444(2025,-990) 445(2025,-980) 446(2025,-970) 447(2025,-960) 448(2025,-950) 449(2025,-940) 450(2025,-930) 451(2025,-920) 452(2025,-910) 453(2025,-900) 454(2025,-890) 455(2025,-880) 456(2025,-870) 457(2025,-860) 458(2025,-850) 459(2025,-840) 460(2025,-830) 461(2025,-820) 462(2025,-810) 463(2025,-800) 464(2025,-790) 465(2025,-780) 466(2025,-770) 467(2025,-760) 468(2025,-750) 469(2025,-740) 470(2025,-730) 471(2025,-720) 472(2025,-710) 473(2025,-700) 474(2025,-690) 475(2025,-680) 476(2025,-670) 477(2025,-660) 478(2025,-650) 479(2025,-640) 480(2025,-630) 481(2025,-620) 482(2025,-610) 483(2025,-600) 484(2025,-590) 485(2025,-580) 486(2025,-570) 487(2025,-560) 488(2025,-550) 489(2025,-540) 490(2025,-530) 491(2025,-520) 492(2025,-510) 493(2025,-500) 494(2025,-490) 495(2025,-480) 496(2025,-470) 497(2025,-460) 498(2025,-450) 499(2025,-440) 500(2025,-430) 501(2025,-420) 502(2025,-410) 503(2025,-400) 504(2025,-390) 505(2025,-380) 506(2025,-370) 507(2025,-360) 508(2025,-350) 509(2025,-340) 510(2025,-330) 511(2025,-320) 512(2025,-310) 513(2025,-300) 514(2025,-290) 515(2025,-280) 516(2025,-270) 517(2025,-260) 518(2025,-250) 519(2025,-240) 520(2025,-230) 521(2025,-220) 522(2025,-210) 523(2025,-200) 524(2025,-190) 525(2025,-180) 526(2025,-170) 527(2025,-160) 528(2025,-150) 529(2025,-140) 530(2025,-130) 531(2025,-120) 532(2025,-110) 533(2025,-100) 534(2025,-90) 535(2025,-80) 536(2025,-70) 537(2025,-60) 538(2025,-50) 539(2025,-40) 540(2025,-30) 541(2025,-20) 542(2025,-10) 543(2025,0)
  oval 5x75 smd: 182(113,-1912) 183(123,-1912) 184(133,-1912) 185(143,-1912) 186(153,-1912) 187(163,-1912) 188(173,-1912) 189(183,-1912) 190(193,-1912) 191(203,-1912) 192(213,-1912) 193(223,-1912) 194(233,-1912) 195(243,-1912) 196(253,-1912) 197(263,-1912) 198(273,-1912) 199(283,-1912) 200(293,-1912) 201(303,-1912) 202(313,-1912) 203(323,-1912) 204(333,-1912) 205(343,-1912) 206(353,-1912) 207(363,-1912) 208(373,-1912) 209(383,-1912) 210(393,-1912) 211(403,-1912) 212(413,-1912) 213(423,-1912) 214(433,-1912) 215(443,-1912) 216(453,-1912) 217(463,-1912) 218(473,-1912) 219(483,-1912) 220(493,-1912) 221(503,-1912) 222(513,-1912) 223(523,-1912) 224(533,-1912) 225(543,-1912) 226(553,-1912) 227(563,-1912) 228(573,-1912) 229(583,-1912) 230(593,-1912) 231(603,-1912) 232(613,-1912) 233(623,-1912) 234(633,-1912) 235(643,-1912) 236(653,-1912) 237(663,-1912) 238(673,-1912) 239(683,-1912) 240(693,-1912) 241(703,-1912) 242(713,-1912) 243(723,-1912) 244(733,-1912) 245(743,-1912) 246(753,-1912) 247(763,-1912) 248(773,-1912) 249(783,-1912) 250(793,-1912) 251(803,-1912) 252(813,-1912) 253(823,-1912) 254(833,-1912) 255(843,-1912) 256(853,-1912) 257(863,-1912) 258(873,-1912) 259(883,-1912) 260(893,-1912) 261(903,-1912) 262(913,-1912) 263(923,-1912) 264(933,-1912) 265(943,-1912) 266(953,-1912) 267(963,-1912) 268(973,-1912) 269(983,-1912) 270(993,-1912) 271(1003,-1912) 272(1013,-1912) 273(1023,-1912) 274(1033,-1912) 275(1043,-1912) 276(1053,-1912) 277(1063,-1912) 278(1073,-1912) 279(1083,-1912) 280(1093,-1912) 281(1103,-1912) 282(1113,-1912) 283(1123,-1912) 284(1133,-1912) 285(1143,-1912) 286(1153,-1912) 287(1163,-1912) 288(1173,-1912) 289(1183,-1912) 290(1193,-1912) 291(1203,-1912) 292(1213,-1912) 293(1223,-1912) 294(1233,-1912) 295(1243,-1912) 296(1253,-1912) 297(1263,-1912) 298(1273,-1912) 299(1283,-1912) 300(1293,-1912) 301(1303,-1912) 302(1313,-1912) 303(1323,-1912) 304(1333,-1912) 305(1343,-1912) 306(1353,-1912) 307(1363,-1912) 308(1373,-1912) 309(1383,-1912) 310(1393,-1912) 311(1403,-1912) 312(1413,-1912) 313(1423,-1912) 314(1433,-1912) 315(1443,-1912) 316(1453,-1912) 317(1463,-1912) 318(1473,-1912) 319(1483,-1912) 320(1493,-1912) 321(1503,-1912) 322(1513,-1912) 323(1523,-1912) 324(1533,-1912) 325(1543,-1912) 326(1553,-1912) 327(1563,-1912) 328(1573,-1912) 329(1583,-1912) 330(1593,-1912) 331(1603,-1912) 332(1613,-1912) 333(1623,-1912) 334(1633,-1912) 335(1643,-1912) 336(1653,-1912) 337(1663,-1912) 338(1673,-1912) 339(1683,-1912) 340(1693,-1912) 341(1703,-1912) 342(1713,-1912) 343(1723,-1912) 344(1733,-1912) 345(1743,-1912) 346(1753,-1912) 347(1763,-1912) 348(1773,-1912) 349(1783,-1912) 350(1793,-1912) 351(1803,-1912) 352(1813,-1912) 353(1823,-1912) 354(1833,-1912) 355(1843,-1912) 356(1853,-1912) 357(1863,-1912) 358(1873,-1912) 359(1883,-1912) 360(1893,-1912) 361(1903,-1912) 362(1913,-1912) 544(1913,113) 545(1903,113) 546(1893,113) 547(1883,113) 548(1873,113) 549(1863,113) 550(1853,113) 551(1843,113) 552(1833,113) 553(1823,113) 554(1813,113) 555(1803,113) 556(1793,113) 557(1783,113) 558(1773,113) 559(1763,113) 560(1753,113) 561(1743,113) 562(1733,113) 563(1723,113) 564(1713,113) 565(1703,113) 566(1693,113) 567(1683,113) 568(1673,113) 569(1663,113) 570(1653,113) 571(1643,113) 572(1633,113) 573(1623,113) 574(1613,113) 575(1603,113) 576(1593,113) 577(1583,113) 578(1573,113) 579(1563,113) 580(1553,113) 581(1543,113) 582(1533,113) 583(1523,113) 584(1513,113) 585(1503,113) 586(1493,113) 587(1483,113) 588(1473,113) 589(1463,113) 590(1453,113) 591(1443,113) 592(1433,113) 593(1423,113) 594(1413,113) 595(1403,113) 596(1393,113) 597(1383,113) 598(1373,113) 599(1363,113) 600(1353,113) 601(1343,113) 602(1333,113) 603(1323,113) 604(1313,113) 605(1303,113) 606(1293,113) 607(1283,113) 608(1273,113) 609(1263,113) 610(1253,113) 611(1243,113) 612(1233,113) 613(1223,113) 614(1213,113) 615(1203,113) 616(1193,113) 617(1183,113) 618(1173,113) 619(1163,113) 620(1153,113) 621(1143,113) 622(1133,113) 623(1123,113) 624(1113,113) 625(1103,113) 626(1093,113) 627(1083,113) 628(1073,113) 629(1063,113) 630(1053,113) 631(1043,113) 632(1033,113) 633(1023,113) 634(1013,113) 635(1003,113) 636(993,113) 637(983,113) 638(973,113) 639(963,113) 640(953,113) 641(943,113) 642(933,113) 643(923,113) 644(913,113) 645(903,113) 646(893,113) 647(883,113) 648(873,113) 649(863,113) 650(853,113) 651(843,113) 652(833,113) 653(823,113) 654(813,113) 655(803,113) 656(793,113) 657(783,113) 658(773,113) 659(763,113) 660(753,113) 661(743,113) 662(733,113) 663(723,113) 664(713,113) 665(703,113) 666(693,113) 667(683,113) 668(673,113) 669(663,113) 670(653,113) 671(643,113) 672(633,113) 673(623,113) 674(613,113) 675(603,113) 676(593,113) 677(583,113) 678(573,113) 679(563,113) 680(553,113) 681(543,113) 682(533,113) 683(523,113) 684(513,113) 685(503,113) 686(493,113) 687(483,113) 688(473,113) 689(463,113) 690(453,113) 691(443,113) 692(433,113) 693(423,113) 694(413,113) 695(403,113) 696(393,113) 697(383,113) 698(373,113) 699(363,113) 700(353,113) 701(343,113) 702(333,113) 703(323,113) 704(313,113) 705(303,113) 706(293,113) 707(283,113) 708(273,113) 709(263,113) 710(253,113) 711(243,113) 712(233,113) 713(223,113) 714(213,113) 715(203,113) 716(193,113) 717(183,113) 718(173,113) 719(163,113) 720(153,113) 721(143,113) 722(133,113) 723(123,113) 724(113,113)

## TAPE804-10 [mil]
pads (804):
  oval 75x5 smd: 1(0,0) 2(0,-10) 3(0,-20) 4(0,-30) 5(0,-40) 6(0,-50) 7(0,-60) 8(0,-70) 9(0,-80) 10(0,-90) 11(0,-100) 12(0,-110) 13(0,-120) 14(0,-130) 15(0,-140) 16(0,-150) 17(0,-160) 18(0,-170) 19(0,-180) 20(0,-190) 21(0,-200) 22(0,-210) 23(0,-220) 24(0,-230) 25(0,-240) 26(0,-250) 27(0,-260) 28(0,-270) 29(0,-280) 30(0,-290) 31(0,-300) 32(0,-310) 33(0,-320) 34(0,-330) 35(0,-340) 36(0,-350) 37(0,-360) 38(0,-370) 39(0,-380) 40(0,-390) 41(0,-400) 42(0,-410) 43(0,-420) 44(0,-430) 45(0,-440) 46(0,-450) 47(0,-460) 48(0,-470) 49(0,-480) 50(0,-490) 51(0,-500) 52(0,-510) 53(0,-520) 54(0,-530) 55(0,-540) 56(0,-550) 57(0,-560) 58(0,-570) 59(0,-580) 60(0,-590) 61(0,-600) 62(0,-610) 63(0,-620) 64(0,-630) 65(0,-640) 66(0,-650) 67(0,-660) 68(0,-670) 69(0,-680) 70(0,-690) 71(0,-700) 72(0,-710) 73(0,-720) 74(0,-730) 75(0,-740) 76(0,-750) 77(0,-760) 78(0,-770) 79(0,-780) 80(0,-790) 81(0,-800) 82(0,-810) 83(0,-820) 84(0,-830) 85(0,-840) 86(0,-850) 87(0,-860) 88(0,-870) 89(0,-880) 90(0,-890) 91(0,-900) 92(0,-910) 93(0,-920) 94(0,-930) 95(0,-940) 96(0,-950) 97(0,-960) 98(0,-970) 99(0,-980) 100(0,-990) 101(0,-1000) 102(0,-1010) 103(0,-1020) 104(0,-1030) 105(0,-1040) 106(0,-1050) 107(0,-1060) 108(0,-1070) 109(0,-1080) 110(0,-1090) 111(0,-1100) 112(0,-1110) 113(0,-1120) 114(0,-1130) 115(0,-1140) 116(0,-1150) 117(0,-1160) 118(0,-1170) 119(0,-1180) 120(0,-1190) 121(0,-1200) 122(0,-1210) 123(0,-1220) 124(0,-1230) 125(0,-1240) 126(0,-1250) 127(0,-1260) 128(0,-1270) 129(0,-1280) 130(0,-1290) 131(0,-1300) 132(0,-1310) 133(0,-1320) 134(0,-1330) 135(0,-1340) 136(0,-1350) 137(0,-1360) 138(0,-1370) 139(0,-1380) 140(0,-1390) 141(0,-1400) 142(0,-1410) 143(0,-1420) 144(0,-1430) 145(0,-1440) 146(0,-1450) 147(0,-1460) 148(0,-1470) 149(0,-1480) 150(0,-1490) 151(0,-1500) 152(0,-1510) 153(0,-1520) 154(0,-1530) 155(0,-1540) 156(0,-1550) 157(0,-1560) 158(0,-1570) 159(0,-1580) 160(0,-1590) 161(0,-1600) 162(0,-1610) 163(0,-1620) 164(0,-1630) 165(0,-1640) 166(0,-1650) 167(0,-1660) 168(0,-1670) 169(0,-1680) 170(0,-1690) 171(0,-1700) 172(0,-1710) 173(0,-1720) 174(0,-1730) 175(0,-1740) 176(0,-1750) 177(0,-1760) 178(0,-1770) 179(0,-1780) 180(0,-1790) 181(0,-1800) 182(0,-1810) 183(0,-1820) 184(0,-1830) 185(0,-1840) 186(0,-1850) 187(0,-1860) 188(0,-1870) 189(0,-1880) 190(0,-1890) 191(0,-1900) 192(0,-1910) 193(0,-1920) 194(0,-1930) 195(0,-1940) 196(0,-1950) 197(0,-1960) 198(0,-1970) 199(0,-1980) 200(0,-1990) 201(0,-2000) 403(2225,-2000) 404(2225,-1990) 405(2225,-1980) 406(2225,-1970) 407(2225,-1960) 408(2225,-1950) 409(2225,-1940) 410(2225,-1930) 411(2225,-1920) 412(2225,-1910) 413(2225,-1900) 414(2225,-1890) 415(2225,-1880) 416(2225,-1870) 417(2225,-1860) 418(2225,-1850) 419(2225,-1840) 420(2225,-1830) 421(2225,-1820) 422(2225,-1810) 423(2225,-1800) 424(2225,-1790) 425(2225,-1780) 426(2225,-1770) 427(2225,-1760) 428(2225,-1750) 429(2225,-1740) 430(2225,-1730) 431(2225,-1720) 432(2225,-1710) 433(2225,-1700) 434(2225,-1690) 435(2225,-1680) 436(2225,-1670) 437(2225,-1660) 438(2225,-1650) 439(2225,-1640) 440(2225,-1630) 441(2225,-1620) 442(2225,-1610) 443(2225,-1600) 444(2225,-1590) 445(2225,-1580) 446(2225,-1570) 447(2225,-1560) 448(2225,-1550) 449(2225,-1540) 450(2225,-1530) 451(2225,-1520) 452(2225,-1510) 453(2225,-1500) 454(2225,-1490) 455(2225,-1480) 456(2225,-1470) 457(2225,-1460) 458(2225,-1450) 459(2225,-1440) 460(2225,-1430) 461(2225,-1420) 462(2225,-1410) 463(2225,-1400) 464(2225,-1390) 465(2225,-1380) 466(2225,-1370) 467(2225,-1360) 468(2225,-1350) 469(2225,-1340) 470(2225,-1330) 471(2225,-1320) 472(2225,-1310) 473(2225,-1300) 474(2225,-1290) 475(2225,-1280) 476(2225,-1270) 477(2225,-1260) 478(2225,-1250) 479(2225,-1240) 480(2225,-1230) 481(2225,-1220) 482(2225,-1210) 483(2225,-1200) 484(2225,-1190) 485(2225,-1180) 486(2225,-1170) 487(2225,-1160) 488(2225,-1150) 489(2225,-1140) 490(2225,-1130) 491(2225,-1120) 492(2225,-1110) 493(2225,-1100) 494(2225,-1090) 495(2225,-1080) 496(2225,-1070) 497(2225,-1060) 498(2225,-1050) 499(2225,-1040) 500(2225,-1030) 501(2225,-1020) 502(2225,-1010) 503(2225,-1000) 504(2225,-990) 505(2225,-980) 506(2225,-970) 507(2225,-960) 508(2225,-950) 509(2225,-940) 510(2225,-930) 511(2225,-920) 512(2225,-910) 513(2225,-900) 514(2225,-890) 515(2225,-880) 516(2225,-870) 517(2225,-860) 518(2225,-850) 519(2225,-840) 520(2225,-830) 521(2225,-820) 522(2225,-810) 523(2225,-800) 524(2225,-790) 525(2225,-780) 526(2225,-770) 527(2225,-760) 528(2225,-750) 529(2225,-740) 530(2225,-730) 531(2225,-720) 532(2225,-710) 533(2225,-700) 534(2225,-690) 535(2225,-680) 536(2225,-670) 537(2225,-660) 538(2225,-650) 539(2225,-640) 540(2225,-630) 541(2225,-620) 542(2225,-610) 543(2225,-600) 544(2225,-590) 545(2225,-580) 546(2225,-570) 547(2225,-560) 548(2225,-550) 549(2225,-540) 550(2225,-530) 551(2225,-520) 552(2225,-510) 553(2225,-500) 554(2225,-490) 555(2225,-480) 556(2225,-470) 557(2225,-460) 558(2225,-450) 559(2225,-440) 560(2225,-430) 561(2225,-420) 562(2225,-410) 563(2225,-400) 564(2225,-390) 565(2225,-380) 566(2225,-370) 567(2225,-360) 568(2225,-350) 569(2225,-340) 570(2225,-330) 571(2225,-320) 572(2225,-310) 573(2225,-300) 574(2225,-290) 575(2225,-280) 576(2225,-270) 577(2225,-260) 578(2225,-250) 579(2225,-240) 580(2225,-230) 581(2225,-220) 582(2225,-210) 583(2225,-200) 584(2225,-190) 585(2225,-180) 586(2225,-170) 587(2225,-160) 588(2225,-150) 589(2225,-140) 590(2225,-130) 591(2225,-120) 592(2225,-110) 593(2225,-100) 594(2225,-90) 595(2225,-80) 596(2225,-70) 597(2225,-60) 598(2225,-50) 599(2225,-40) 600(2225,-30) 601(2225,-20) 602(2225,-10) 603(2225,0)
  oval 5x75 smd: 202(113,-2112) 203(123,-2112) 204(133,-2112) 205(143,-2112) 206(153,-2112) 207(163,-2112) 208(173,-2112) 209(183,-2112) 210(193,-2112) 211(203,-2112) 212(213,-2112) 213(223,-2112) 214(233,-2112) 215(243,-2112) 216(253,-2112) 217(263,-2112) 218(273,-2112) 219(283,-2112) 220(293,-2112) 221(303,-2112) 222(313,-2112) 223(323,-2112) 224(333,-2112) 225(343,-2112) 226(353,-2112) 227(363,-2112) 228(373,-2112) 229(383,-2112) 230(393,-2112) 231(403,-2112) 232(413,-2112) 233(423,-2112) 234(433,-2112) 235(443,-2112) 236(453,-2112) 237(463,-2112) 238(473,-2112) 239(483,-2112) 240(493,-2112) 241(503,-2112) 242(513,-2112) 243(523,-2112) 244(533,-2112) 245(543,-2112) 246(553,-2112) 247(563,-2112) 248(573,-2112) 249(583,-2112) 250(593,-2112) 251(603,-2112) 252(613,-2112) 253(623,-2112) 254(633,-2112) 255(643,-2112) 256(653,-2112) 257(663,-2112) 258(673,-2112) 259(683,-2112) 260(693,-2112) 261(703,-2112) 262(713,-2112) 263(723,-2112) 264(733,-2112) 265(743,-2112) 266(753,-2112) 267(763,-2112) 268(773,-2112) 269(783,-2112) 270(793,-2112) 271(803,-2112) 272(813,-2112) 273(823,-2112) 274(833,-2112) 275(843,-2112) 276(853,-2112) 277(863,-2112) 278(873,-2112) 279(883,-2112) 280(893,-2112) 281(903,-2112) 282(913,-2112) 283(923,-2112) 284(933,-2112) 285(943,-2112) 286(953,-2112) 287(963,-2112) 288(973,-2112) 289(983,-2112) 290(993,-2112) 291(1003,-2112) 292(1013,-2112) 293(1023,-2112) 294(1033,-2112) 295(1043,-2112) 296(1053,-2112) 297(1063,-2112) 298(1073,-2112) 299(1083,-2112) 300(1093,-2112) 301(1103,-2112) 302(1113,-2112) 303(1123,-2112) 304(1133,-2112) 305(1143,-2112) 306(1153,-2112) 307(1163,-2112) 308(1173,-2112) 309(1183,-2112) 310(1193,-2112) 311(1203,-2112) 312(1213,-2112) 313(1223,-2112) 314(1233,-2112) 315(1243,-2112) 316(1253,-2112) 317(1263,-2112) 318(1273,-2112) 319(1283,-2112) 320(1293,-2112) 321(1303,-2112) 322(1313,-2112) 323(1323,-2112) 324(1333,-2112) 325(1343,-2112) 326(1353,-2112) 327(1363,-2112) 328(1373,-2112) 329(1383,-2112) 330(1393,-2112) 331(1403,-2112) 332(1413,-2112) 333(1423,-2112) 334(1433,-2112) 335(1443,-2112) 336(1453,-2112) 337(1463,-2112) 338(1473,-2112) 339(1483,-2112) 340(1493,-2112) 341(1503,-2112) 342(1513,-2112) 343(1523,-2112) 344(1533,-2112) 345(1543,-2112) 346(1553,-2112) 347(1563,-2112) 348(1573,-2112) 349(1583,-2112) 350(1593,-2112) 351(1603,-2112) 352(1613,-2112) 353(1623,-2112) 354(1633,-2112) 355(1643,-2112) 356(1653,-2112) 357(1663,-2112) 358(1673,-2112) 359(1683,-2112) 360(1693,-2112) 361(1703,-2112) 362(1713,-2112) 363(1723,-2112) 364(1733,-2112) 365(1743,-2112) 366(1753,-2112) 367(1763,-2112) 368(1773,-2112) 369(1783,-2112) 370(1793,-2112) 371(1803,-2112) 372(1813,-2112) 373(1823,-2112) 374(1833,-2112) 375(1843,-2112) 376(1853,-2112) 377(1863,-2112) 378(1873,-2112) 379(1883,-2112) 380(1893,-2112) 381(1903,-2112) 382(1913,-2112) 383(1923,-2112) 384(1933,-2112) 385(1943,-2112) 386(1953,-2112) 387(1963,-2112) 388(1973,-2112) 389(1983,-2112) 390(1993,-2112) 391(2003,-2112) 392(2013,-2112) 393(2023,-2112) 394(2033,-2112) 395(2043,-2112) 396(2053,-2112) 397(2063,-2112) 398(2073,-2112) 399(2083,-2112) 400(2093,-2112) 401(2103,-2112) 402(2113,-2112) 604(2113,113) 605(2103,113) 606(2093,113) 607(2083,113) 608(2073,113) 609(2063,113) 610(2053,113) 611(2043,113) 612(2033,113) 613(2023,113) 614(2013,113) 615(2003,113) 616(1993,113) 617(1983,113) 618(1973,113) 619(1963,113) 620(1953,113) 621(1943,113) 622(1933,113) 623(1923,113) 624(1913,113) 625(1903,113) 626(1893,113) 627(1883,113) 628(1873,113) 629(1863,113) 630(1853,113) 631(1843,113) 632(1833,113) 633(1823,113) 634(1813,113) 635(1803,113) 636(1793,113) 637(1783,113) 638(1773,113) 639(1763,113) 640(1753,113) 641(1743,113) 642(1733,113) 643(1723,113) 644(1713,113) 645(1703,113) 646(1693,113) 647(1683,113) 648(1673,113) 649(1663,113) 650(1653,113) 651(1643,113) 652(1633,113) 653(1623,113) 654(1613,113) 655(1603,113) 656(1593,113) 657(1583,113) 658(1573,113) 659(1563,113) 660(1553,113) 661(1543,113) 662(1533,113) 663(1523,113) 664(1513,113) 665(1503,113) 666(1493,113) 667(1483,113) 668(1473,113) 669(1463,113) 670(1453,113) 671(1443,113) 672(1433,113) 673(1423,113) 674(1413,113) 675(1403,113) 676(1393,113) 677(1383,113) 678(1373,113) 679(1363,113) 680(1353,113) 681(1343,113) 682(1333,113) 683(1323,113) 684(1313,113) 685(1303,113) 686(1293,113) 687(1283,113) 688(1273,113) 689(1263,113) 690(1253,113) 691(1243,113) 692(1233,113) 693(1223,113) 694(1213,113) 695(1203,113) 696(1193,113) 697(1183,113) 698(1173,113) 699(1163,113) 700(1153,113) 701(1143,113) 702(1133,113) 703(1123,113) 704(1113,113) 705(1103,113) 706(1093,113) 707(1083,113) 708(1073,113) 709(1063,113) 710(1053,113) 711(1043,113) 712(1033,113) 713(1023,113) 714(1013,113) 715(1003,113) 716(993,113) 717(983,113) 718(973,113) 719(963,113) 720(953,113) 721(943,113) 722(933,113) 723(923,113) 724(913,113) 725(903,113) 726(893,113) 727(883,113) 728(873,113) 729(863,113) 730(853,113) 731(843,113) 732(833,113) 733(823,113) 734(813,113) 735(803,113) 736(793,113) 737(783,113) 738(773,113) 739(763,113) 740(753,113) 741(743,113) 742(733,113) 743(723,113) 744(713,113) 745(703,113) 746(693,113) 747(683,113) 748(673,113) 749(663,113) 750(653,113) 751(643,113) 752(633,113) 753(623,113) 754(613,113) 755(603,113) 756(593,113) 757(583,113) 758(573,113) 759(563,113) 760(553,113) 761(543,113) 762(533,113) 763(523,113) 764(513,113) 765(503,113) 766(493,113) 767(483,113) 768(473,113) 769(463,113) 770(453,113) 771(443,113) 772(433,113) 773(423,113) 774(413,113) 775(403,113) 776(393,113) 777(383,113) 778(373,113) 779(363,113) 780(353,113) 781(343,113) 782(333,113) 783(323,113) 784(313,113) 785(303,113) 786(293,113) 787(283,113) 788(273,113) 789(263,113) 790(253,113) 791(243,113) 792(233,113) 793(223,113) 794(213,113) 795(203,113) 796(193,113) 797(183,113) 798(173,113) 799(163,113) 800(153,113) 801(143,113) 802(133,113) 803(123,113) 804(113,113)

## TO-3 [mil]
pads (4):
  round 150 hole 28: 1(0,0) 2(0,430) 3(-525,215) 3(665,215)
TopOverlay:
  circle w10: c73,215 r415
  circle w10: c665,215 r95
  circle w10: c-525,215 r95
  lines w12: -677,165 -27,-250 173,-250 823,165 823,265 173,675 -27,675 -677,265 -677,165

## TO-5 [mil]
pads (3):
  round 60 hole 30: 1(0,0) 2(-100,100) 3(-200,0)
TopOverlay:
  circle w10: c-100,0 r160
  lines w8: 0,-130 20,-150 40,-130 20,-110

## TO-18 [mil]
pads (3):
  round 60 hole 30: 1(0,0) 2(-50,50) 3(-100,0)
TopOverlay:
  circle w10: c-50,0 r100
  lines w8: 10,-80 30,-100 50,-80 30,-60

## TO-39 [mil]
pads (3):
  round 60 hole 30: 1(0,0) 2(-100,100) 3(-200,0)
TopOverlay:
  circle w10: c-100,0 r160
  lines w8: 0,-130 20,-150 40,-130 20,-110

## TO-46 [mil]
pads (3):
  round 60 hole 30: 1(0,0) 2(-50,50) 3(-100,0)
TopOverlay:
  circle w10: c-50,0 r100
  lines w8: 10,-80 30,-100 50,-80 30,-60

## TO-52 [mil]
pads (3):
  round 60 hole 30: 1(0,0) 2(-50,50) 3(-100,0)
TopOverlay:
  circle w10: c-50,0 r100
  lines w8: 10,-80 30,-100 50,-80 30,-60

## TO-66 [mil]
pads (4):
  round 100 hole 28: 1(0,200) 2(0,0) 3(-380,100) 3(580,100)
TopOverlay:
  circle w10: c100,100 r250
  circle w10: c-380,100 r80
  circle w10: c580,100 r80
  lines w12: -500,-10 -500,190 0,450 200,450 700,200 700,0 200,-250 0,-250 -500,-10

## TO-72 [mil]
pads (4):
  round 60 hole 30: 1(0,0) 2(-50,50) 3(-100,0)
  round 50 hole 30: 4(-50,-50)
TopOverlay:
  circle w10: c-50,0 r100
  lines w8: 10,-80 30,-100 50,-80 30,-60

## TO-92A [mil]
pads (3):
  round 50 hole 30: 1(0,0) 2(50,-50) 3(100,0)
TopOverlay:
  lines w8: -40,-40 -40,40 140,40 140,-40 90,-90 10,-90 -40,-40

## TO-92B [mil]
pads (3):
  oval 40x60 hole 30: 1(0,0) 2(50,0) 3(100,0)
TopOverlay:
  lines w8: -40,-40 -40,40 140,40 140,-40 90,-90 10,-90 -40,-40

## TO-126 [mil]
pads (3):
  round 62 hole 28: 1(-200,0) 2(-100,0) 3(0,0)
TopOverlay:
  lines w12: -250,-50 -250,50 50,50 50,-50 -250,-50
